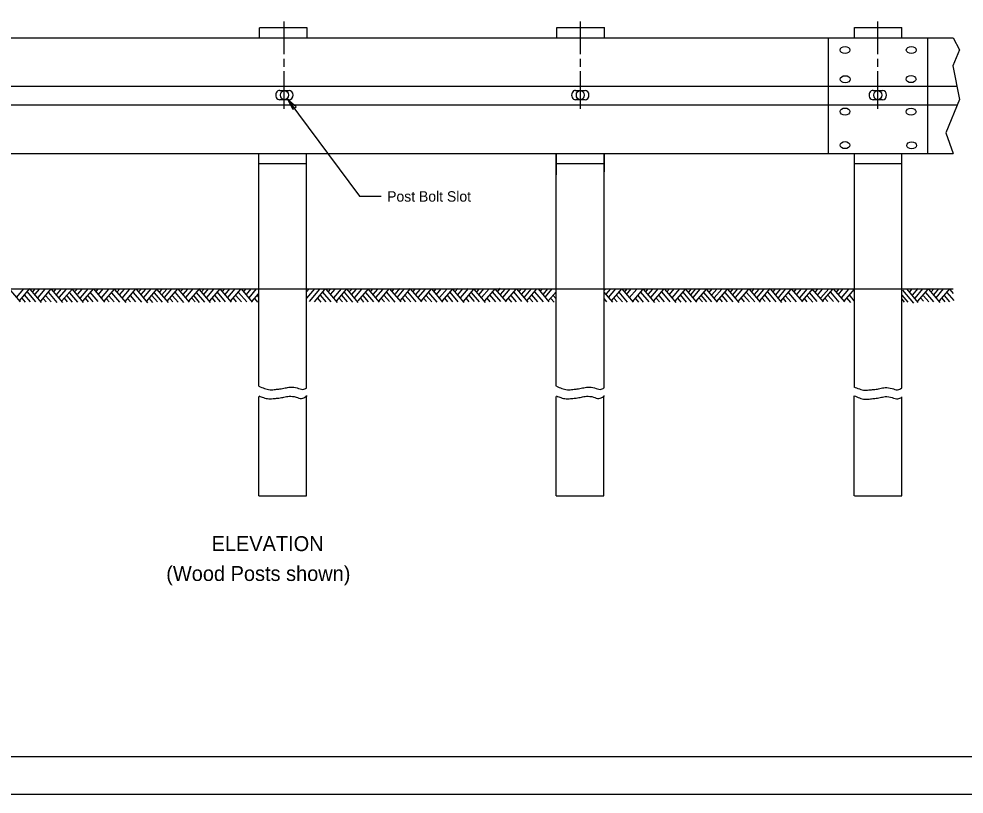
# Model space of a CAD drawing. Extents: x 0 to 34, y 0 to 22.
# Drawn here: x 9.94 to 22.61, y 0 to 10.38 of the extents above; entities that cross this region are included whole.
import ezdxf

# ---------------------------------------------------------------- set-up
doc = ezdxf.new("R2010")
doc.units = 0
for name, color, linetype in [('SH_Border', 7, 'Continuous'), ('SH_Cut_Line', 7, 'Continuous'), ('ST_Details', 7, 'Continuous'), ('ST_Text', 7, 'Continuous')]:
    doc.layers.add(name, color=color, linetype=linetype)

msp = doc.modelspace()

# ---------------------------------------------------------------- linework, layer by layer
at = {"layer": 'SH_Border'}
msp.add_lwpolyline([(1.5, 21.5), (33.5, 21.5), (33.5, 0.5), (1.5, 0.5)], close=True, dxfattribs=at)
at = {"layer": 'SH_Cut_Line'}
msp.add_lwpolyline([(0, 0), (34, 0), (34, 22), (0, 22)], close=True, dxfattribs=at)
at = {"layer": 'ST_Details'}
for p, q in [((13.167, 10.264), (13.805, 10.264)), ((13.167, 10.129), (13.167, 10.263)), ((13.497, 9.909), (13.497, 10.344)), ((13.805, 10.129), (13.805, 10.263)), ((17.151, 10.264), (17.789, 10.264)), ((17.151, 10.129), (17.151, 10.264)), ((17.469, 9.909), (17.469, 10.344)), ((17.789, 10.129), (17.789, 10.264)), ((21.136, 10.264), (21.773, 10.264)), ((21.136, 10.129), (21.136, 10.264)), ((21.453, 9.909), (21.453, 10.344)), ((21.773, 10.129), (21.773, 10.264)), ((3.972, 10.129), (22.458, 10.129)), ((20.789, 8.576), (20.789, 10.129)), ((22.121, 8.577), (22.121, 10.129)), ((22.458, 10.129), (22.546, 9.966)), ((22.546, 9.966), (22.454, 9.75)), ((13.497, 9.738), (13.497, 9.847)), ((17.469, 9.738), (17.469, 9.847)), ((21.453, 9.738), (21.453, 9.847)), ((13.497, 9.176), (13.497, 9.681)), ((17.469, 9.176), (17.469, 9.681)), ((21.453, 9.176), (21.453, 9.681)), ((22.454, 9.75), (22.546, 9.303)), ((4.185, 9.48), (22.518, 9.48)), ((13.438, 9.423), (13.501, 9.423)), ((13.501, 9.423), (13.564, 9.423)), ((17.402, 9.423), (17.465, 9.423)), ((17.465, 9.423), (17.528, 9.423)), ((21.387, 9.423), (21.45, 9.423)), ((21.45, 9.423), (21.514, 9.423)), ((13.501, 9.298), (13.438, 9.298)), ((13.564, 9.298), (13.501, 9.298)), ((17.465, 9.298), (17.402, 9.298)), ((17.528, 9.298), (17.465, 9.298)), ((21.45, 9.298), (21.387, 9.298)), ((21.514, 9.298), (21.45, 9.298)), ((22.546, 9.303), (22.363, 8.857)), ((4.153, 9.228), (22.515, 9.228)), ((22.363, 8.857), (22.458, 8.576)), ((3.972, 8.576), (22.458, 8.576)), ((13.158, 5.461), (13.158, 8.576)), ((13.799, 5.437), (13.799, 8.576)), ((17.142, 6.762), (17.142, 8.576)), ((17.142, 8.576), (17.142, 8.293)), ((17.783, 5.437), (17.783, 8.576)), ((17.783, 8.576), (17.783, 8.331)), ((21.136, 5.453), (21.136, 8.577)), ((21.773, 5.437), (21.773, 8.576)), ((13.158, 8.444), (13.799, 8.444)), ((17.142, 8.444), (17.783, 8.444)), ((21.136, 8.444), (21.773, 8.444)), ((3.972, 6.764), (22.458, 6.764)), ((9.965, 6.593), (9.814, 6.769)), ((9.816, 6.764), (13.158, 6.764)), ((9.914, 6.651), (10.011, 6.765)), ((9.952, 6.607), (10.092, 6.772)), ((10.17, 6.592), (10.054, 6.729)), ((10.248, 6.585), (10.097, 6.762)), ((10.129, 6.725), (10.163, 6.765)), ((10.16, 6.695), (10.218, 6.763)), ((10.2, 6.651), (10.296, 6.763)), ((10.238, 6.6), (10.378, 6.765)), ((10.456, 6.585), (10.343, 6.718)), ((10.531, 6.585), (10.38, 6.762)), ((10.415, 6.732), (10.439, 6.76)), ((10.446, 6.684), (10.515, 6.765)), ((10.484, 6.648), (10.582, 6.763)), ((10.521, 6.604), (10.66, 6.767)), ((10.733, 6.588), (10.626, 6.714)), ((10.811, 6.585), (10.66, 6.762)), ((10.695, 6.728), (10.725, 6.763)), ((10.732, 6.695), (10.79, 6.763)), ((10.77, 6.644), (10.873, 6.765)), ((10.804, 6.604), (10.943, 6.767)), ((11.007, 6.596), (10.9, 6.722)), ((11.097, 6.589), (10.947, 6.766)), ((10.981, 6.732), (11.008, 6.763)), ((11.012, 6.692), (11.075, 6.765)), ((11.05, 6.644), (11.149, 6.761)), ((11.087, 6.6), (11.224, 6.761)), ((11.296, 6.588), (11.189, 6.714)), ((11.38, 6.582), (11.23, 6.758)), ((11.261, 6.725), (11.296, 6.765)), ((11.298, 6.688), (11.359, 6.76)), ((11.326, 6.64), (11.425, 6.756)), ((11.367, 6.596), (11.51, 6.765)), ((11.589, 6.588), (11.479, 6.718)), ((11.672, 6.578), (11.522, 6.755)), ((11.55, 6.728), (11.58, 6.763)), ((11.582, 6.688), (11.646, 6.763)), ((11.613, 6.644), (11.717, 6.767)), ((11.653, 6.596), (11.797, 6.765)), ((11.867, 6.587), (11.759, 6.714)), ((11.946, 6.582), (11.796, 6.758)), ((11.83, 6.725), (11.863, 6.763)), ((11.858, 6.684), (11.926, 6.763)), ((11.896, 6.651), (11.992, 6.765)), ((11.93, 6.6), (12.072, 6.767)), ((12.155, 6.585), (12.042, 6.718)), ((12.229, 6.589), (12.079, 6.766)), ((12.11, 6.728), (12.14, 6.763)), ((12.145, 6.692), (12.206, 6.763)), ((12.179, 6.648), (12.279, 6.765)), ((12.222, 6.6), (12.366, 6.769)), ((12.433, 6.587), (12.325, 6.715)), ((12.512, 6.582), (12.362, 6.758)), ((12.39, 6.725), (12.425, 6.765)), ((12.421, 6.692), (12.486, 6.767)), ((12.462, 6.651), (12.557, 6.763)), ((12.502, 6.604), (12.641, 6.767)), ((12.713, 6.591), (12.603, 6.721)), ((12.79, 6.587), (12.64, 6.764)), ((12.67, 6.728), (12.704, 6.768)), ((12.707, 6.688), (12.771, 6.764)), ((12.741, 6.649), (12.84, 6.765)), ((12.78, 6.6), (12.919, 6.763)), ((12.996, 6.59), (12.886, 6.719)), ((13.075, 6.587), (12.925, 6.764)), ((12.958, 6.728), (12.989, 6.765)), ((12.993, 6.688), (13.057, 6.764)), ((13.027, 6.647), (13.128, 6.766)), ((13.799, 6.724), (13.834, 6.766)), ((13.799, 6.764), (17.142, 6.764)), ((13.803, 6.643), (13.909, 6.767)), ((13.835, 6.596), (13.974, 6.76)), ((13.902, 6.593), (14.041, 6.756)), ((14.128, 6.59), (14.016, 6.721)), ((14.21, 6.583), (14.06, 6.76)), ((14.091, 6.728), (14.124, 6.766)), ((14.12, 6.688), (14.183, 6.763)), ((14.163, 6.647), (14.264, 6.766)), ((14.198, 6.602), (14.337, 6.765)), ((14.416, 6.589), (14.304, 6.721)), ((14.491, 6.585), (14.341, 6.762)), ((14.374, 6.729), (14.402, 6.762)), ((14.404, 6.689), (14.464, 6.759)), ((14.443, 6.648), (14.54, 6.762)), ((14.488, 6.604), (14.627, 6.768)), ((14.7, 6.592), (14.592, 6.719)), ((14.775, 6.588), (14.625, 6.765)), ((14.657, 6.729), (14.687, 6.764)), ((14.692, 6.689), (14.753, 6.76)), ((14.727, 6.648), (14.825, 6.763)), ((14.766, 6.602), (14.905, 6.765)), ((14.985, 6.588), (14.867, 6.726)), ((15.065, 6.59), (14.915, 6.767)), ((14.943, 6.732), (14.97, 6.764)), ((14.987, 6.699), (15.048, 6.771)), ((15.015, 6.653), (15.107, 6.761)), ((15.054, 6.61), (15.189, 6.769)), ((15.266, 6.592), (15.153, 6.724)), ((15.34, 6.59), (15.19, 6.767)), ((15.227, 6.732), (15.254, 6.763)), ((15.262, 6.691), (15.323, 6.763)), ((15.295, 6.648), (15.392, 6.762)), ((15.333, 6.602), (15.472, 6.765)), ((15.548, 6.587), (15.435, 6.719)), ((15.624, 6.588), (15.474, 6.765)), ((15.505, 6.732), (15.531, 6.763)), ((15.539, 6.691), (15.602, 6.765)), ((15.58, 6.648), (15.681, 6.766)), ((15.617, 6.605), (15.756, 6.768)), ((15.83, 6.593), (15.721, 6.721)), ((15.908, 6.585), (15.758, 6.762)), ((15.788, 6.729), (15.822, 6.769)), ((15.825, 6.686), (15.892, 6.764)), ((15.86, 6.645), (15.968, 6.772)), ((15.899, 6.597), (16.038, 6.76)), ((16.115, 6.594), (16.009, 6.719)), ((16.194, 6.585), (16.044, 6.762)), ((16.081, 6.729), (16.11, 6.763)), ((16.109, 6.691), (16.171, 6.764)), ((16.142, 6.648), (16.242, 6.766)), ((16.185, 6.604), (16.324, 6.768)), ((16.399, 6.596), (16.289, 6.726)), ((16.476, 6.59), (16.326, 6.767)), ((16.357, 6.726), (16.398, 6.775)), ((16.397, 6.688), (16.458, 6.76)), ((16.427, 6.65), (16.526, 6.765)), ((16.468, 6.599), (16.606, 6.763)), ((16.683, 6.596), (16.577, 6.72)), ((16.765, 6.587), (16.615, 6.764)), ((16.646, 6.729), (16.676, 6.764)), ((16.678, 6.691), (16.738, 6.761)), ((16.718, 6.655), (16.807, 6.76)), ((16.749, 6.605), (16.884, 6.764)), ((16.971, 6.591), (16.856, 6.726)), ((17.049, 6.593), (16.903, 6.764)), ((16.927, 6.729), (16.958, 6.766)), ((16.97, 6.694), (17.03, 6.765)), ((16.995, 6.655), (17.087, 6.764)), ((17.04, 6.608), (17.141, 6.727)), ((17.142, 5.461), (17.142, 6.762)), ((17.782, 6.74), (17.801, 6.762)), ((17.783, 6.764), (21.136, 6.764)), ((17.9, 6.587), (17.784, 6.723)), ((17.813, 6.694), (17.872, 6.764)), ((17.843, 6.65), (17.941, 6.765)), ((17.883, 6.605), (18.022, 6.768)), ((18.098, 6.587), (17.985, 6.72)), ((18.176, 6.587), (18.026, 6.764)), ((18.059, 6.723), (18.094, 6.764)), ((18.084, 6.688), (18.148, 6.764)), ((18.119, 6.644), (18.22, 6.762)), ((18.164, 6.593), (18.303, 6.757)), ((18.387, 6.59), (18.274, 6.723)), ((18.462, 6.584), (18.312, 6.761)), ((18.343, 6.726), (18.375, 6.765)), ((18.373, 6.688), (18.437, 6.763)), ((18.41, 6.65), (18.51, 6.767)), ((18.446, 6.599), (18.584, 6.763)), ((18.67, 6.59), (18.56, 6.72)), ((18.748, 6.584), (18.598, 6.761)), ((18.624, 6.726), (18.659, 6.768)), ((18.659, 6.691), (18.721, 6.764)), ((18.697, 6.647), (18.797, 6.765)), ((18.734, 6.599), (18.873, 6.763)), ((18.955, 6.588), (18.841, 6.723)), ((19.027, 6.587), (18.876, 6.764)), ((18.919, 6.723), (18.952, 6.762)), ((18.948, 6.689), (19.01, 6.761)), ((18.977, 6.651), (19.072, 6.763)), ((19.018, 6.599), (19.157, 6.763)), ((19.226, 6.591), (19.121, 6.715)), ((19.303, 6.587), (19.159, 6.757)), ((19.193, 6.719), (19.232, 6.765)), ((19.228, 6.685), (19.292, 6.761)), ((19.26, 6.644), (19.359, 6.761)), ((19.295, 6.596), (19.434, 6.759)), ((19.513, 6.59), (19.404, 6.719)), ((19.592, 6.583), (19.442, 6.76)), ((19.476, 6.723), (19.511, 6.764)), ((19.508, 6.685), (19.576, 6.766)), ((19.546, 6.651), (19.642, 6.764)), ((19.581, 6.596), (19.72, 6.759)), ((19.802, 6.59), (19.692, 6.719)), ((19.881, 6.587), (19.73, 6.763)), ((19.768, 6.733), (19.798, 6.769)), ((19.8, 6.689), (19.861, 6.76)), ((19.829, 6.647), (19.922, 6.757)), ((19.87, 6.606), (20.008, 6.769)), ((20.091, 6.59), (19.975, 6.726)), ((20.166, 6.583), (20.016, 6.76)), ((20.051, 6.73), (20.079, 6.764)), ((20.083, 6.685), (20.148, 6.762)), ((20.118, 6.644), (20.216, 6.76)), ((20.153, 6.599), (20.291, 6.763)), ((20.359, 6.593), (20.258, 6.712)), ((20.447, 6.59), (20.296, 6.767)), ((20.331, 6.726), (20.362, 6.764)), ((20.363, 6.685), (20.429, 6.764)), ((20.404, 6.644), (20.504, 6.762)), ((20.442, 6.603), (20.58, 6.766)), ((20.638, 6.595), (20.536, 6.715)), ((20.724, 6.59), (20.573, 6.767)), ((20.614, 6.723), (20.648, 6.764)), ((20.643, 6.682), (20.711, 6.762)), ((20.689, 6.644), (20.793, 6.765)), ((20.71, 6.599), (20.849, 6.763)), ((20.935, 6.588), (20.821, 6.722)), ((21.01, 6.59), (20.859, 6.767)), ((20.897, 6.723), (20.934, 6.767)), ((20.926, 6.692), (20.984, 6.76)), ((20.964, 6.647), (21.061, 6.762)), ((21.002, 6.599), (21.14, 6.763)), ((21.773, 6.764), (22.458, 6.764)), ((21.935, 6.573), (21.784, 6.75)), ((21.993, 6.583), (21.843, 6.76)), ((21.88, 6.726), (21.912, 6.764)), ((21.915, 6.682), (21.992, 6.772)), ((21.95, 6.641), (22.055, 6.764)), ((21.988, 6.599), (22.127, 6.763)), ((22.203, 6.59), (22.094, 6.719)), ((22.285, 6.583), (22.135, 6.76)), ((22.166, 6.726), (22.2, 6.767)), ((22.201, 6.685), (22.268, 6.764)), ((22.233, 6.647), (22.332, 6.764)), ((22.277, 6.603), (22.415, 6.766)), ((22.473, 6.609), (22.38, 6.719)), ((22.464, 6.705), (22.42, 6.757)), ((10.033, 6.588), (9.989, 6.641)), ((10.099, 6.592), (10.02, 6.685)), ((10.309, 6.59), (10.268, 6.638)), ((10.377, 6.59), (10.306, 6.674)), ((10.595, 6.594), (10.555, 6.641)), ((10.662, 6.588), (10.589, 6.674)), ((10.878, 6.59), (10.835, 6.641)), ((10.94, 6.594), (10.872, 6.674)), ((11.153, 6.592), (11.118, 6.634)), ((11.22, 6.59), (11.149, 6.674)), ((11.44, 6.592), (11.404, 6.634)), ((11.511, 6.592), (11.438, 6.678)), ((11.738, 6.585), (11.693, 6.638)), ((11.8, 6.592), (11.727, 6.678)), ((12.007, 6.59), (11.97, 6.634)), ((12.076, 6.587), (12.001, 6.674)), ((12.304, 6.592), (12.266, 6.638)), ((12.365, 6.583), (12.291, 6.671)), ((12.576, 6.593), (12.536, 6.64)), ((12.644, 6.59), (12.568, 6.679)), ((12.859, 6.591), (12.818, 6.64)), ((12.924, 6.591), (12.851, 6.677)), ((13.07, 6.6), (13.155, 6.701)), ((13.145, 6.589), (13.104, 6.638)), ((13.157, 6.656), (13.139, 6.677)), ((13.993, 6.589), (13.949, 6.64)), ((14.061, 6.59), (13.983, 6.681)), ((14.278, 6.591), (14.235, 6.642)), ((14.345, 6.59), (14.269, 6.679)), ((14.566, 6.589), (14.523, 6.64)), ((14.626, 6.593), (14.555, 6.675)), ((14.841, 6.59), (14.798, 6.64)), ((14.908, 6.595), (14.837, 6.678)), ((15.125, 6.591), (15.086, 6.637)), ((15.193, 6.59), (15.119, 6.678)), ((15.403, 6.596), (15.368, 6.637)), ((15.476, 6.59), (15.4, 6.678)), ((15.692, 6.592), (15.65, 6.642)), ((15.759, 6.593), (15.684, 6.681)), ((15.978, 6.592), (15.94, 6.637)), ((16.047, 6.595), (15.975, 6.68)), ((16.256, 6.592), (16.216, 6.64)), ((16.333, 6.591), (16.253, 6.684)), ((16.548, 6.588), (16.504, 6.64)), ((16.609, 6.594), (16.537, 6.678)), ((16.829, 6.592), (16.785, 6.643)), ((16.897, 6.592), (16.816, 6.687)), ((17.114, 6.587), (17.072, 6.637)), ((17.142, 6.631), (17.102, 6.678)), ((17.822, 6.59), (17.783, 6.636)), ((17.96, 6.59), (17.915, 6.643)), ((18.028, 6.59), (17.95, 6.681)), ((18.247, 6.589), (18.204, 6.64)), ((18.313, 6.589), (18.239, 6.675)), ((18.524, 6.591), (18.485, 6.637)), ((18.594, 6.591), (18.52, 6.678)), ((18.817, 6.589), (18.773, 6.64)), ((18.887, 6.589), (18.806, 6.684)), ((19.101, 6.591), (19.056, 6.643)), ((19.16, 6.59), (19.083, 6.681)), ((19.371, 6.593), (19.328, 6.643)), ((19.439, 6.591), (19.366, 6.678)), ((19.665, 6.593), (19.625, 6.64)), ((19.732, 6.59), (19.657, 6.678)), ((19.942, 6.597), (19.902, 6.643)), ((20.015, 6.593), (19.937, 6.684)), ((20.224, 6.592), (20.185, 6.636)), ((20.285, 6.592), (20.215, 6.674)), ((20.505, 6.593), (20.468, 6.636)), ((20.58, 6.588), (20.506, 6.674)), ((20.781, 6.595), (20.74, 6.643)), ((20.857, 6.595), (20.786, 6.678)), ((21.087, 6.585), (21.035, 6.647)), ((21.135, 6.607), (21.07, 6.684)), ((21.856, 6.587), (21.776, 6.681)), ((21.808, 6.588), (21.776, 6.626)), ((22.062, 6.599), (22.026, 6.64)), ((22.136, 6.59), (22.064, 6.674)), ((22.353, 6.592), (22.312, 6.64)), ((22.416, 6.59), (22.342, 6.678)), ((13.158, 3.994), (13.158, 5.322)), ((13.79, 5.331), (13.805, 5.331)), ((13.795, 3.994), (13.795, 5.327)), ((17.142, 3.994), (17.142, 5.322)), ((17.775, 5.331), (17.789, 5.331)), ((17.78, 3.994), (17.78, 5.327)), ((21.133, 3.994), (21.133, 5.333)), ((21.773, 3.994), (21.773, 5.319)), ((13.158, 3.993), (13.795, 3.993)), ((17.142, 3.993), (17.78, 3.993)), ((21.136, 3.996), (21.773, 3.996))]:
    msp.add_line(p, q, dxfattribs=at)
for centre, major_axis, ratio in [((21.011, 9.964), (-0.0664, 0), 0.705181), ((21.899, 9.964), (-0.0664, 0), 0.705181), ((21.014, 9.573), (-0.0664, 0), 0.705181), ((21.896, 9.574), (-0.0664, 0), 0.705181), ((13.501, 9.361), (0, 0.0625), 0.850089), ((17.465, 9.361), (0, 0.0625), 0.850089), ((21.45, 9.361), (0, 0.0625), 0.850089), ((21.011, 9.14), (-0.0664, 0), 0.705181), ((21.896, 9.137), (-0.0664, 0), 0.705181), ((21.011, 8.69), (-0.0664, 0), 0.705181), ((21.904, 8.687), (-0.0664, 0), 0.705181)]:
    msp.add_ellipse(centre, major_axis=major_axis, ratio=ratio, dxfattribs=at)
for centre, start_param, end_param in [((13.438, 9.361), 0, 3.141593), ((13.564, 9.361), 3.141593, 6.283185), ((17.402, 9.361), 0, 3.141593), ((17.528, 9.361), 3.141593, 6.283185), ((21.387, 9.361), 0, 3.141593), ((21.514, 9.361), 3.141593, 6.283185)]:
    msp.add_ellipse(centre, major_axis=(0, 0.0625), ratio=0.850089, start_param=start_param, end_param=end_param, dxfattribs=at)
for points in [[(13.16, 5.461), (13.234, 5.432), (13.308, 5.414), (13.382, 5.42), (13.441, 5.426), (13.51, 5.438), (13.579, 5.449), (13.673, 5.438), (13.747, 5.42), (13.798, 5.44)], [(17.145, 5.461), (17.218, 5.432), (17.292, 5.414), (17.366, 5.42), (17.425, 5.426), (17.494, 5.438), (17.563, 5.449), (17.657, 5.438), (17.731, 5.42), (17.782, 5.44)], [(21.129, 5.454), (21.203, 5.425), (21.277, 5.408), (21.35, 5.414), (21.41, 5.419), (21.479, 5.431), (21.548, 5.443), (21.641, 5.431), (21.715, 5.414), (21.774, 5.437)], [(13.164, 5.331), (13.219, 5.31), (13.293, 5.293), (13.367, 5.298), (13.426, 5.304), (13.495, 5.316), (13.564, 5.327), (13.657, 5.316), (13.731, 5.298), (13.79, 5.322)], [(17.148, 5.331), (17.203, 5.31), (17.277, 5.293), (17.351, 5.298), (17.41, 5.304), (17.479, 5.316), (17.548, 5.327), (17.641, 5.316), (17.715, 5.298), (17.775, 5.322)], [(21.132, 5.334), (21.205, 5.305), (21.279, 5.287), (21.353, 5.293), (21.412, 5.299), (21.481, 5.31), (21.55, 5.322), (21.644, 5.31), (21.718, 5.293), (21.772, 5.314)]]:
    msp.add_spline(points, degree=3, dxfattribs=at)
at = {"layer": 'ST_Text'}
msp.add_lwpolyline([(13.548, 9.298), (14.508, 8.005), (14.799, 8.005)], dxfattribs=at)
msp.add_lwpolyline([(13.657, 9.205), (13.548, 9.298), (13.612, 9.17)], close=True, dxfattribs=at)

# ---------------------------------------------------------------- texts
for s, height, p in [('Post Bolt Slot', 0.14, (14.877, 7.933)), ('ELEVATION', 0.2, (12.525, 3.254)), ('(Wood Posts shown)', 0.2, (11.918, 2.854))]:
    msp.add_text(s, height=height, dxfattribs=at).set_placement(p)

doc.saveas('drawing.dxf')
